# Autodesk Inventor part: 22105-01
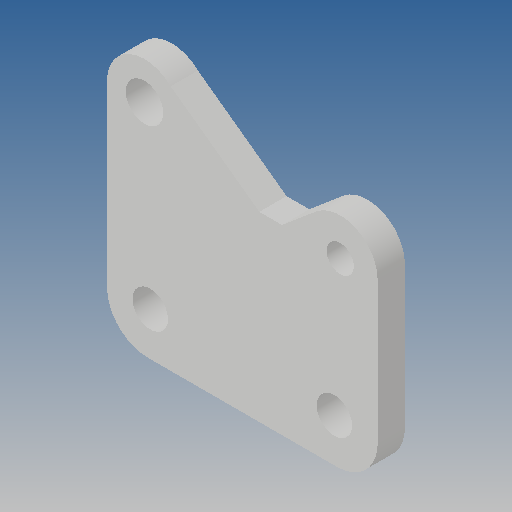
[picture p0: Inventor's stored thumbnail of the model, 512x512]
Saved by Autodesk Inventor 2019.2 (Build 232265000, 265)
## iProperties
Created: 2017-06
Part Number: 22105-01
Material: Ogólny
Document SubType Name: Modeling
Designer: CADENGINEERING4
Density: 1 g/cm^3
Appearance: Domyślna
Author: CADENGINEERING4
Revision Number: ÈÎºÎ
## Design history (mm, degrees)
feature "Í¹Ì¨-À­Éì1"
node "Bryła1"
